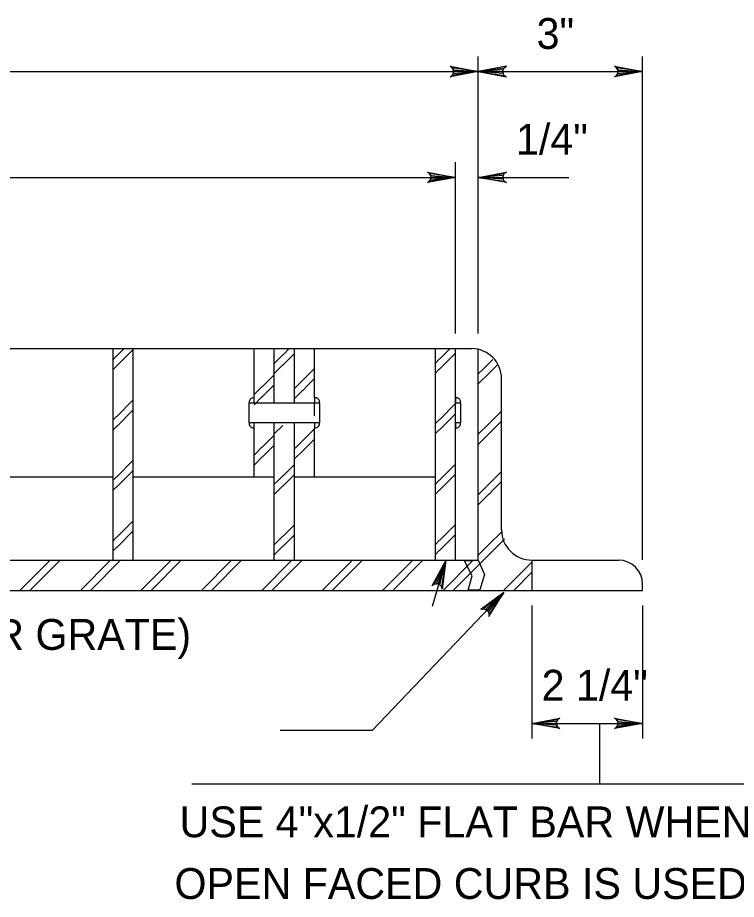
# Model space of a CAD drawing. Extents: x 0.71 to 8.05, y -5.67 to 4.31.
# Drawn here: x 2.981 to 4.38, y -1.774 to -0.058 of the extents above; entities that cross this region are included whole.
import ezdxf

# ---------------------------------------------------------------- set-up
doc = ezdxf.new("R2010")
doc.units = 0
for name, color, linetype in [('DETL-DIMS', 7, 'Continuous'), ('DETL-LINE', 7, 'Continuous'), ('DETL-NOTE', 7, 'Continuous'), ('DETL-PATT', 7, 'Continuous')]:
    doc.layers.add(name, color=color, linetype=linetype)

msp = doc.modelspace()

# ---------------------------------------------------------------- linework, layer by layer
at = {"layer": 'DETL-DIMS'}
for p, q in [((3.8775, -0.6723), (3.8775, -0.1331)), ((4.1976, -1.1129), (4.1976, -0.1331)), ((1.2402, -0.1625), (3.8775, -0.1625)), ((3.8775, -0.1625), (4.1976, -0.1625)), ((3.8334, -0.6723), (3.8334, -0.339)), ((1.2844, -0.3684), (3.8334, -0.3684)), ((3.8775, -0.3684), (4.054, -0.3684)), ((3.7885, -1.2028), (3.8143, -1.1143)), ((3.6719, -1.4447), (3.9276, -1.1763)), ((3.9819, -1.2017), (3.9819, -1.4606)), ((4.1976, -1.2017), (4.1976, -1.4606)), ((3.9819, -1.4312), (4.1976, -1.4312)), ((4.1138, -1.4312), (4.1138, -1.5488)), ((3.4917, -1.4447), (3.6719, -1.4447)), ((3.3197, -1.5488), (4.6432, -1.5488))]:
    msp.add_line(p, q, dxfattribs=at)
for points in [[(3.8775, -0.1625), (3.8227, -0.1728), (3.8269, -0.1699), (3.8291, -0.1662), (3.8297, -0.1625), (3.8291, -0.1588), (3.8269, -0.1552), (3.8227, -0.1522), (3.8775, -0.1625), (3.8269, -0.1552), (3.8291, -0.1588), (3.8775, -0.1625), (3.8297, -0.1625), (3.8291, -0.1662), (3.8775, -0.1625), (3.8269, -0.1699)], [(3.8775, -0.1625), (3.9323, -0.1728), (3.9281, -0.1699), (3.9259, -0.1662), (3.9253, -0.1625), (3.9259, -0.1588), (3.9281, -0.1552), (3.9323, -0.1522), (3.8775, -0.1625), (3.9281, -0.1552), (3.9259, -0.1588), (3.8775, -0.1625), (3.9253, -0.1625), (3.9259, -0.1662), (3.8775, -0.1625), (3.9281, -0.1699)], [(4.1976, -0.1625), (4.1428, -0.1728), (4.147, -0.1699), (4.1492, -0.1662), (4.1498, -0.1625), (4.1492, -0.1588), (4.147, -0.1552), (4.1428, -0.1522), (4.1976, -0.1625), (4.147, -0.1552), (4.1492, -0.1588), (4.1976, -0.1625), (4.1498, -0.1625), (4.1492, -0.1662), (4.1976, -0.1625), (4.147, -0.1699)], [(3.8334, -0.3684), (3.7786, -0.3787), (3.7828, -0.3758), (3.785, -0.3721), (3.7856, -0.3684), (3.785, -0.3647), (3.7828, -0.3611), (3.7786, -0.3581), (3.8334, -0.3684), (3.7828, -0.3611), (3.785, -0.3647), (3.8334, -0.3684), (3.7856, -0.3684), (3.785, -0.3721), (3.8334, -0.3684), (3.7828, -0.3758)], [(3.8775, -0.3684), (3.9323, -0.3581), (3.9281, -0.3611), (3.9259, -0.3647), (3.9253, -0.3684), (3.9259, -0.3721), (3.9281, -0.3758), (3.9323, -0.3787), (3.8775, -0.3684), (3.9281, -0.3758), (3.9259, -0.3721), (3.8775, -0.3684), (3.9253, -0.3684), (3.9259, -0.3647), (3.8775, -0.3684), (3.9281, -0.3611)], [(3.8143, -1.1143), (3.8074, -1.1697), (3.8059, -1.1648), (3.8031, -1.1616), (3.7998, -1.1599), (3.7961, -1.1594), (3.7919, -1.1603), (3.7878, -1.1635), (3.8143, -1.1143), (3.7919, -1.1603), (3.7961, -1.1594), (3.8143, -1.1143), (3.7998, -1.1599), (3.8031, -1.1616), (3.8143, -1.1143), (3.8059, -1.1648)], [(3.9276, -1.1763), (3.8828, -1.2096), (3.8878, -1.2084), (3.892, -1.2093), (3.8952, -1.2114), (3.8974, -1.2143), (3.8986, -1.2184), (3.8979, -1.2235), (3.9276, -1.1763), (3.8986, -1.2184), (3.8974, -1.2143), (3.9276, -1.1763), (3.8952, -1.2114), (3.892, -1.2093), (3.9276, -1.1763), (3.8878, -1.2084)], [(3.9819, -1.4312), (4.0367, -1.4209), (4.0325, -1.4238), (4.0303, -1.4275), (4.0297, -1.4312), (4.0303, -1.4348), (4.0325, -1.4385), (4.0367, -1.4414), (3.9819, -1.4312), (4.0325, -1.4385), (4.0303, -1.4348), (3.9819, -1.4312), (4.0297, -1.4312), (4.0303, -1.4275), (3.9819, -1.4312), (4.0325, -1.4238)], [(4.1976, -1.4312), (4.1428, -1.4414), (4.147, -1.4385), (4.1492, -1.4348), (4.1498, -1.4312), (4.1492, -1.4275), (4.147, -1.4238), (4.1428, -1.4209), (4.1976, -1.4312), (4.147, -1.4238), (4.1492, -1.4275), (4.1976, -1.4312), (4.1498, -1.4312), (4.1492, -1.4348), (4.1976, -1.4312), (4.147, -1.4385)]]:
    msp.add_lwpolyline(points, dxfattribs=at)
at = {"layer": 'DETL-LINE'}
for p, q in [((1.2535, -0.7017), (3.8643, -0.7017)), ((3.1667, -1.1135), (3.1667, -0.7017)), ((3.2059, -1.1135), (3.2059, -0.7017)), ((3.4412, -0.7971), (3.4412, -0.7017)), ((3.4804, -0.8071), (3.4804, -0.7017)), ((3.5197, -0.8071), (3.5197, -0.7017)), ((3.5589, -0.7974), (3.5589, -0.7017)), ((3.7942, -1.1135), (3.7942, -0.7017)), ((3.8334, -1.1135), (3.8334, -0.7017)), ((3.8775, -1.1135), (3.8775, -0.7017)), ((3.9231, -1.0547), (3.9231, -0.7606)), ((3.5589, -0.8326), (3.5589, -0.8071)), ((3.4412, -0.9517), (3.4412, -0.8561)), ((3.4804, -1.1135), (3.4804, -0.8463)), ((3.5197, -1.1135), (3.5197, -0.8463)), ((3.5589, -0.9517), (3.5589, -0.8562)), ((3.1667, -0.9517), (2.8922, -0.9517)), ((3.4804, -0.9517), (3.2059, -0.9517)), ((3.7942, -0.9517), (3.5197, -0.9517)), ((1.2402, -1.1135), (3.8775, -1.1135)), ((3.9819, -1.1135), (3.9819, -1.1723)), ((3.9819, -1.1135), (4.1505, -1.1135)), ((4.1976, -1.1723), (4.1976, -1.1606)), ((0.9201, -1.1723), (3.9819, -1.1723)), ((3.9819, -1.1723), (4.1976, -1.1723))]:
    msp.add_line(p, q, dxfattribs=at)
for points in [[(3.4412, -0.7973), (3.4396, -0.7974), (3.4378, -0.7977), (3.4365, -0.7982), (3.4356, -0.7987), (3.4346, -0.7995), (3.4337, -0.8003), (3.4327, -0.8017), (3.4319, -0.8033), (3.4316, -0.8047), (3.4314, -0.806), (3.4315, -0.8071), (3.4412, -0.8071)], [(3.5687, -0.8071), (3.5686, -0.8055), (3.5683, -0.8037), (3.5678, -0.8024), (3.5673, -0.8015), (3.5665, -0.8005), (3.5657, -0.7996), (3.5643, -0.7986), (3.5627, -0.7978), (3.5613, -0.7975), (3.56, -0.7973), (3.5589, -0.7974), (3.5589, -0.8071)], [(3.8433, -0.8071), (3.8432, -0.8054), (3.8429, -0.8037), (3.8424, -0.8024), (3.8419, -0.8014), (3.8411, -0.8004), (3.8403, -0.7996), (3.8389, -0.7986), (3.8373, -0.7977), (3.8359, -0.7974), (3.8346, -0.7972), (3.8335, -0.7973), (3.8335, -0.8071)], [(3.5686, -0.8463), (3.4315, -0.8463), (3.4315, -0.8071), (3.5686, -0.8071)], [(3.8432, -0.8463), (3.8335, -0.8463), (3.8335, -0.8071), (3.8432, -0.8071)], [(3.4314, -0.8463), (3.4315, -0.848), (3.4318, -0.8497), (3.4323, -0.8511), (3.4328, -0.852), (3.4336, -0.853), (3.4344, -0.8538), (3.4358, -0.8549), (3.4374, -0.8557), (3.4388, -0.856), (3.4401, -0.8562), (3.4412, -0.8561), (3.4412, -0.8463)], [(3.5589, -0.8562), (3.5605, -0.8561), (3.5623, -0.8558), (3.5636, -0.8553), (3.5645, -0.8548), (3.5655, -0.854), (3.5664, -0.8532), (3.5674, -0.8518), (3.5682, -0.8501), (3.5685, -0.8488), (3.5687, -0.8475), (3.5686, -0.8463), (3.5589, -0.8463)], [(3.8335, -0.8561), (3.8351, -0.8561), (3.8369, -0.8558), (3.8382, -0.8552), (3.8391, -0.8547), (3.8401, -0.8539), (3.841, -0.8532), (3.842, -0.8518), (3.8428, -0.8501), (3.8431, -0.8487), (3.8433, -0.8474), (3.8432, -0.8463), (3.8335, -0.8463)], [(3.8775, -1.1135), (3.8896, -1.1417), (3.8804, -1.1713), (3.858, -1.1718), (3.8656, -1.1442), (3.8508, -1.1146)]]:
    msp.add_lwpolyline(points, close=True, dxfattribs=at)
for centre, radius, start, end in [((3.8643, -0.7606), 0.0588, 0, 90), ((3.9819, -1.0547), 0.0588, 180, 270), ((4.1505, -1.1606), 0.0471, 0, 90)]:
    msp.add_arc(centre, radius, start, end, dxfattribs=at)
at = {"layer": 'DETL-PATT'}
for p, q in [((3.1738, -0.716), (3.1881, -0.7017)), ((3.1836, -0.7258), (3.2059, -0.7035)), ((3.4976, -0.7139), (3.5097, -0.7017)), ((3.8021, -0.7224), (3.8228, -0.7017)), ((3.1667, -0.7227), (3.1734, -0.716)), ((3.4874, -0.7237), (3.4972, -0.7139)), ((3.5074, -0.7237), (3.5197, -0.7114)), ((3.8119, -0.7322), (3.8334, -0.7108)), ((3.1667, -0.7423), (3.1734, -0.7356)), ((3.1836, -0.7258), (3.1734, -0.736)), ((3.4804, -0.7306), (3.4874, -0.7237)), ((3.4804, -0.7502), (3.4972, -0.7335)), ((3.5074, -0.7237), (3.4972, -0.7339)), ((3.7942, -0.73), (3.8017, -0.7224)), ((3.8119, -0.7322), (3.8017, -0.7425)), ((3.8889, -0.7396), (3.8987, -0.7298)), ((3.8991, -0.7298), (3.9057, -0.7232)), ((3.9089, -0.7396), (3.9144, -0.7341)), ((3.4569, -0.7761), (3.4804, -0.7525)), ((3.5362, -0.7632), (3.5589, -0.7406)), ((3.7942, -0.7496), (3.8017, -0.742)), ((3.8775, -0.751), (3.8889, -0.7396)), ((3.8775, -0.7706), (3.8987, -0.7494)), ((3.9089, -0.7396), (3.8987, -0.7498)), ((3.4667, -0.7859), (3.4804, -0.7721)), ((3.526, -0.773), (3.5358, -0.7632)), ((3.546, -0.773), (3.5589, -0.7602)), ((3.4412, -0.7913), (3.4466, -0.7859)), ((3.4466, -0.7859), (3.4565, -0.7761)), ((3.4667, -0.7859), (3.4565, -0.7961)), ((3.5197, -0.7793), (3.526, -0.773)), ((3.5197, -0.799), (3.5358, -0.7828)), ((3.546, -0.773), (3.5358, -0.7832)), ((3.1738, -0.8337), (3.2059, -0.8016)), ((3.4412, -0.8109), (3.4565, -0.7957)), ((3.2059, -0.8212), (3.1738, -0.8533)), ((3.8021, -0.8401), (3.8334, -0.8088)), ((3.8991, -0.8474), (3.9231, -0.8234)), ((3.1667, -0.8403), (3.1734, -0.8337)), ((3.7942, -0.8476), (3.8017, -0.8401)), ((3.8334, -0.8284), (3.8021, -0.8597)), ((3.1667, -0.86), (3.1734, -0.8533)), ((3.4804, -0.8679), (3.4972, -0.8511)), ((3.8775, -0.8686), (3.8987, -0.8474)), ((3.9231, -0.8431), (3.8991, -0.867)), ((3.4569, -0.8937), (3.4804, -0.8702)), ((3.5362, -0.8809), (3.5589, -0.8582)), ((3.7942, -0.8672), (3.8017, -0.8597)), ((3.8775, -0.8882), (3.8987, -0.867)), ((3.4804, -0.8898), (3.4569, -0.9133)), ((3.5197, -0.897), (3.5358, -0.8809)), ((3.5589, -0.8778), (3.5362, -0.9005)), ((3.4412, -0.909), (3.4565, -0.8937)), ((3.5197, -0.9166), (3.5358, -0.9005)), ((3.1738, -0.9513), (3.2059, -0.9192)), ((3.4412, -0.9286), (3.4565, -0.9133)), ((3.8021, -0.9577), (3.8334, -0.9265)), ((3.1836, -0.9611), (3.2059, -0.9388)), ((3.4976, -0.9492), (3.5197, -0.9271)), ((3.8991, -0.9651), (3.9231, -0.9411)), ((3.1667, -0.958), (3.1734, -0.9513)), ((3.4804, -0.9659), (3.4874, -0.959)), ((3.4874, -0.959), (3.4972, -0.9492)), ((3.5074, -0.959), (3.4972, -0.9692)), ((3.5074, -0.959), (3.5197, -0.9467)), ((3.7942, -0.9653), (3.8017, -0.9577)), ((3.8119, -0.9675), (3.8334, -0.9461)), ((3.9089, -0.9749), (3.9231, -0.9607)), ((3.1667, -0.9776), (3.1734, -0.9709)), ((3.1836, -0.9611), (3.1734, -0.9713)), ((3.4804, -0.9855), (3.4972, -0.9688)), ((3.7942, -0.9849), (3.8017, -0.9773)), ((3.8119, -0.9675), (3.8017, -0.9778)), ((3.8775, -0.9862), (3.8889, -0.9749)), ((3.8889, -0.9749), (3.8987, -0.9651)), ((3.9089, -0.9749), (3.8987, -0.9851)), ((3.8775, -1.0059), (3.8987, -0.9847)), ((3.1738, -1.0689), (3.2059, -1.0369)), ((3.4976, -1.0668), (3.5197, -1.0448)), ((3.8021, -1.0754), (3.8334, -1.0441)), ((3.2059, -1.0565), (3.1738, -1.0886)), ((3.8334, -1.0637), (3.8021, -1.095)), ((3.8991, -1.0827), (3.924, -1.0578)), ((3.1667, -1.0756), (3.1734, -1.0689)), ((3.4804, -1.0836), (3.4972, -1.0668)), ((3.5197, -1.0644), (3.4976, -1.0864)), ((3.7942, -1.0829), (3.8017, -1.0754)), ((3.9286, -1.0728), (3.8991, -1.1023)), ((3.1667, -1.0952), (3.1734, -1.0886)), ((3.4804, -1.1032), (3.4972, -1.0864)), ((3.7942, -1.1025), (3.8017, -1.095)), ((3.8775, -1.1039), (3.8987, -1.0827)), ((2.9851, -1.1723), (3.0439, -1.1135)), ((3.0047, -1.1723), (3.0635, -1.1135)), ((3.1028, -1.1723), (3.1616, -1.1135)), ((3.1224, -1.1723), (3.1812, -1.1135)), ((3.2208, -1.1723), (3.2797, -1.1135)), ((3.2404, -1.1723), (3.2993, -1.1135)), ((3.3385, -1.1723), (3.3973, -1.1135)), ((3.3581, -1.1723), (3.4169, -1.1135)), ((3.4561, -1.1723), (3.5149, -1.1135)), ((3.4757, -1.1723), (3.5346, -1.1135)), ((3.5738, -1.1723), (3.6326, -1.1135)), ((3.5934, -1.1723), (3.6522, -1.1135)), ((3.6914, -1.1723), (3.7502, -1.1135)), ((3.711, -1.1723), (3.7699, -1.1135)), ((3.8091, -1.1723), (3.8679, -1.1135)), ((3.8287, -1.1723), (3.8987, -1.1023)), ((3.9271, -1.1723), (3.9819, -1.1176)), ((3.9468, -1.1723), (3.9819, -1.1372))]:
    msp.add_line(p, q, dxfattribs=at)

# ---------------------------------------------------------------- texts
at = {"layer": 'DETL-NOTE'}
for s, p in [('3"', (3.9912, -0.1184)), ('1/4"', (3.9511, -0.3243)), ('3 1/2"x3/8"x3\'-11 1/4" BEARING BARS(9 PER GRATE)', (1.3448, -1.2881)), ('2 1/4"', (4.001, -1.387)), ('USE 4"x1/2" FLAT BAR WHEN', (3.296, -1.6529)), ('OPEN FACED CURB IS USED.', (3.2861, -1.7729))]:
    msp.add_text(s, height=0.06, dxfattribs=at).set_placement(p)

doc.saveas('drawing.dxf')
